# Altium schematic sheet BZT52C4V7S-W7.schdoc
size 127 x 101 mm
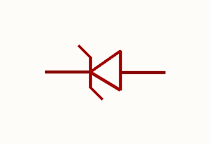
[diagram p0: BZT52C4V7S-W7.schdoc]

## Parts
D?  bzt52c4v7s_c364304  [SOD-323_L1.8-W1.3-LS2.5-RD]  (value not drawn)

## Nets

Not connected (* = marked no-connect by the designer): D? 1 2

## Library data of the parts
D? = bzt52c4v7s_c364304: 二极管配置:1个独立式;稳压值(标称值):4.7V;稳压值(范围值):4.4V~5V;耗散功率(Pd):200mW;; Manufacturer: MDD(辰达半导体); Symbol: BZT52C4V7S-W7; AddInBom: yes; ModelId: db63db13d9e342eb939127d413d6200b; ModelTransform: 104.3305,51.181,0,0,0,0,0,-0.004,0; Diode Configuration: 1个独立式; Zener Voltage(Nom): 4.7V; Reverse Leakage Current (Ir): 2uA@1V; Pd - Power Dissipation: 200mW; Impedance(Zzt): 130Ω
